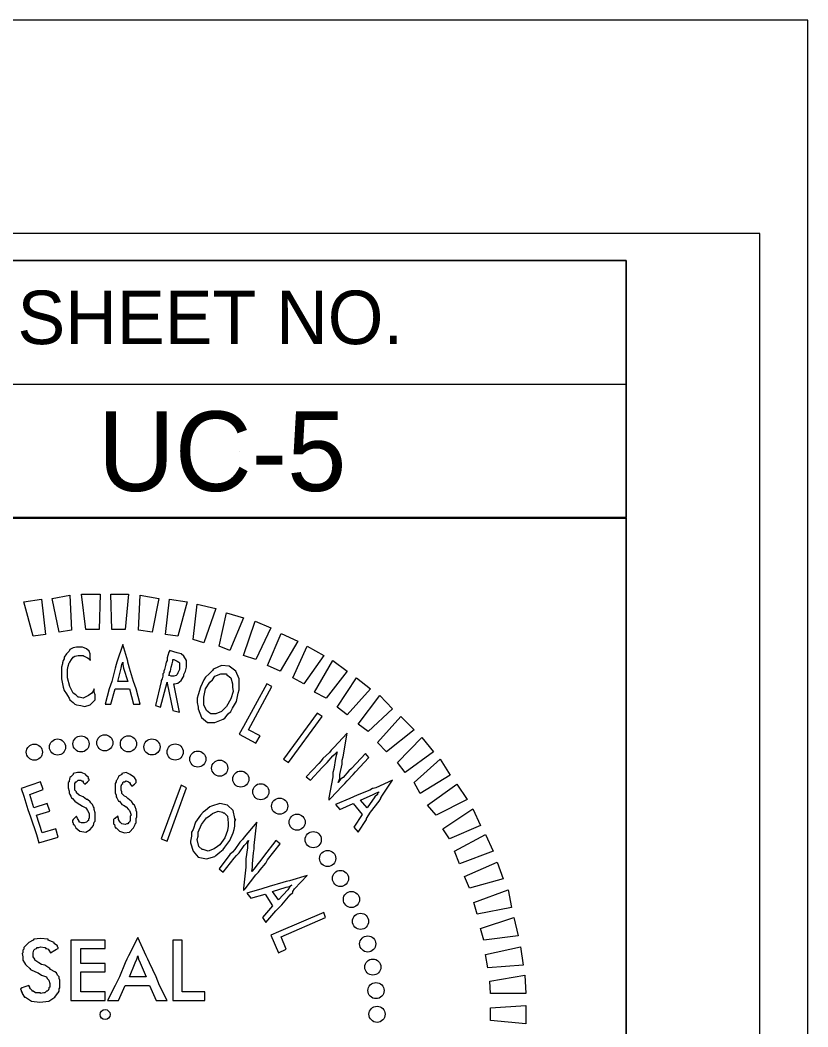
# Model space of a CAD drawing. Extents: x 0 to 2694, y -1 to 1501.
# Drawn here: x 2.7104 to 2.8333, y 1.6762 to 1.8333 of the extents above; entities that cross this region are included whole.
import ezdxf

# ---------------------------------------------------------------- set-up
doc = ezdxf.new("R2010")
doc.units = 0
for name, color, linetype in [('Air Release (M2) CELL', 7, 'Continuous'), ('COGO Default Point Elevation', 7, 'Continuous'), ('Diamond Pattern CELL', 7, 'Continuous')]:
    doc.layers.add(name, color=color, linetype=linetype)

msp = doc.modelspace()

# ---------------------------------------------------------------- linework, layer by layer
at = {"layer": 'Air Release (M2) CELL'}
for p, q in [((2.4719, 1.77648), (2.80496, 1.77648)), ((2.74467, 1.76604), (2.74467, 1.76604)), ((2.72369, 1.67808), (2.72369, 1.67808))]:
    msp.add_line(p, q, dxfattribs=at)
for points in [[(2.4719, 1.79581), (2.80496, 1.79581), (2.80496, 1.75568)], [(2.80496, 1.75568), (2.4719, 1.75568), (2.4719, 1.79581)], [(2.80496, 1.56775), (2.63979, 1.56775), (2.63979, 1.7556), (2.80496, 1.7556)], [(2.80496, 1.7556), (2.80496, 1.56775)]]:
    msp.add_lwpolyline(points, dxfattribs=at)
at = {"layer": 'COGO Default Point Elevation'}
for points in [[(0.02749, 0.00833), (2.83333, 0.00833), (2.83333, 1.83333), (0.02749, 1.83333)], [(0.04916, 0.04166), (2.82583, 0.04166), (2.82583, 1.8), (0.04916, 1.8)], [(2.80499, 1.79583), (0.30499, 1.79583), (0.30499, 0.04583), (2.80499, 0.04583)]]:
    msp.add_lwpolyline(points, close=True, dxfattribs=at)
at = {"layer": 'Diamond Pattern CELL'}
for points in [[(2.7165, 1.73781), (2.71545, 1.74304), (2.7182, 1.74357), (2.71846, 1.73808)], [(2.72068, 1.73821), (2.72003, 1.7437), (2.7229, 1.7437), (2.72277, 1.73821)], [(2.72473, 1.73821), (2.7246, 1.7437), (2.72735, 1.7437), (2.72683, 1.73821)], [(2.72892, 1.73808), (2.72918, 1.74357), (2.73205, 1.74304), (2.73101, 1.73781)], [(2.71245, 1.73716), (2.71101, 1.74252), (2.71376, 1.74291), (2.71441, 1.73742)], [(2.7331, 1.73742), (2.73375, 1.74291), (2.7365, 1.74252), (2.73506, 1.73716)], [(2.73741, 1.73664), (2.73807, 1.74213), (2.74094, 1.74147), (2.73911, 1.73612)], [(2.74147, 1.73559), (2.74264, 1.74082), (2.74526, 1.74004), (2.74317, 1.73494)], [(2.74526, 1.73415), (2.74709, 1.73951), (2.74957, 1.73847), (2.74722, 1.7335)], [(2.74905, 1.73259), (2.75114, 1.73755), (2.75375, 1.73638), (2.75101, 1.73167)], [(2.75297, 1.73063), (2.75519, 1.73559), (2.7578, 1.73415), (2.75467, 1.72971)], [(2.75637, 1.7284), (2.75924, 1.73337), (2.76146, 1.73167), (2.7582, 1.72749)], [(2.7599, 1.72605), (2.7629, 1.73063), (2.76512, 1.72893), (2.76146, 1.72487)], [(2.76316, 1.72344), (2.76656, 1.72788), (2.76852, 1.72579), (2.76473, 1.72226)], [(2.75676, 1.72514), (2.75153, 1.71795), (2.75231, 1.71742), (2.75754, 1.72461)], [(2.76617, 1.72056), (2.76983, 1.72461), (2.77192, 1.72252), (2.76761, 1.71912)], [(2.76931, 1.71742), (2.7731, 1.72135), (2.77493, 1.71912), (2.77048, 1.71586)], [(2.77192, 1.71429), (2.77597, 1.71795), (2.77754, 1.71546), (2.77284, 1.71259)], [(2.73558, 1.71389), (2.73245, 1.70553), (2.73336, 1.70514), (2.73637, 1.7135)], [(2.77401, 1.71076), (2.77859, 1.71403), (2.78016, 1.71167), (2.77532, 1.70919)], [(2.77637, 1.7071), (2.78107, 1.71023), (2.78225, 1.70762), (2.77741, 1.70553)], [(2.7782, 1.70357), (2.78303, 1.70618), (2.78421, 1.70357), (2.77898, 1.70161)], [(2.77976, 1.69965), (2.78486, 1.70187), (2.78578, 1.69926), (2.78055, 1.69782)], [(2.7812, 1.6956), (2.78656, 1.69756), (2.78708, 1.69481), (2.78172, 1.69377)], [(2.78225, 1.69154), (2.78748, 1.69324), (2.78813, 1.69037), (2.78277, 1.68971)], [(2.78303, 1.68749), (2.78852, 1.68867), (2.78891, 1.68579), (2.78342, 1.6854)], [(2.78369, 1.68331), (2.78918, 1.68422), (2.78931, 1.68135), (2.78382, 1.68135)], [(2.78382, 1.67913), (2.78931, 1.67952), (2.78931, 1.67664), (2.78382, 1.67716)]]:
    msp.add_lwpolyline(points, close=True, dxfattribs=at)
for points in [[(2.72134, 1.73442), (2.72121, 1.73481), (2.72081, 1.7352), (2.72042, 1.73533), (2.72016, 1.73546), (2.71925, 1.73546), (2.71872, 1.73533), (2.7182, 1.73507), (2.71807, 1.73481), (2.71768, 1.73442), (2.71728, 1.73389), (2.71728, 1.73376), (2.71728, 1.73363), (2.71715, 1.73337), (2.71702, 1.73298), (2.71702, 1.73285), (2.71689, 1.73232), (2.71689, 1.7318), (2.71689, 1.73049), (2.71715, 1.72919), (2.71728, 1.72866), (2.71768, 1.72814), (2.71781, 1.72788), (2.71807, 1.72749), (2.7182, 1.72723), (2.71872, 1.72683), (2.71898, 1.72657), (2.71925, 1.72644), (2.7199, 1.72631), (2.72055, 1.72618), (2.72134, 1.72644), (2.7216, 1.7267), (2.72186, 1.72697), (2.72212, 1.72723), (2.72212, 1.72775), (2.72212, 1.72801), (2.72199, 1.7284), (2.72199, 1.72866), (2.72199, 1.72893), (2.72186, 1.72866), (2.7216, 1.72827), (2.72108, 1.72788), (2.72029, 1.72749), (2.71964, 1.72762), (2.71951, 1.72762), (2.71911, 1.72801), (2.71872, 1.72827), (2.71846, 1.7288), (2.7182, 1.72932), (2.71781, 1.73063), (2.71781, 1.73193), (2.71794, 1.73246), (2.71807, 1.73298), (2.7182, 1.73311), (2.71846, 1.7335), (2.71872, 1.73389), (2.71898, 1.73402), (2.71951, 1.73415), (2.72029, 1.73415), (2.72042, 1.73402), (2.72094, 1.73376), (2.72134, 1.7335), (2.72134, 1.73337), (2.72134, 1.7335), (2.72134, 1.73389), (2.72134, 1.73415), (2.72134, 1.73429), (2.72134, 1.73442), (2.72134, 1.73442)], [(2.72722, 1.73311), (2.72722, 1.73324), (2.72643, 1.73585), (2.72552, 1.73311), (2.72539, 1.73272), (2.72526, 1.73219), (2.72473, 1.7301), (2.72434, 1.72893), (2.72369, 1.72657), (2.7246, 1.72657), (2.72526, 1.72893), (2.72748, 1.72893), (2.72813, 1.72657), (2.72918, 1.72657), (2.72853, 1.72893), (2.72813, 1.7301), (2.72748, 1.73219), (2.72735, 1.73272), (2.72722, 1.73311), (2.72722, 1.73311)], [(2.73637, 1.73298), (2.73637, 1.73337), (2.73598, 1.73402), (2.73558, 1.73442), (2.73493, 1.73455), (2.73375, 1.73494), (2.73375, 1.73481), (2.73362, 1.73468), (2.73349, 1.73415), (2.73336, 1.73376), (2.73336, 1.73363), (2.73336, 1.7335), (2.73336, 1.73337), (2.73323, 1.73311), (2.7331, 1.73259), (2.73297, 1.73193), (2.73284, 1.73167), (2.73284, 1.73141), (2.73271, 1.73128), (2.73271, 1.73089), (2.73258, 1.73049), (2.73245, 1.73023), (2.73245, 1.7301), (2.73153, 1.72631), (2.73232, 1.72605), (2.73336, 1.72997), (2.73336, 1.72984), (2.73428, 1.72553), (2.73532, 1.72527), (2.73441, 1.72971), (2.73454, 1.72971), (2.73506, 1.72984), (2.73558, 1.73023), (2.73571, 1.73049), (2.73585, 1.73076), (2.73598, 1.73089), (2.73598, 1.73115), (2.73624, 1.73167), (2.73637, 1.73232), (2.73637, 1.73259), (2.73637, 1.73272), (2.73637, 1.73298)], [(2.72643, 1.73311), (2.72643, 1.73272), (2.72656, 1.73219), (2.72722, 1.7301), (2.72565, 1.7301), (2.72617, 1.73219), (2.7263, 1.73272), (2.72643, 1.73311), (2.72643, 1.73311)], [(2.73441, 1.7335), (2.73493, 1.73324), (2.73519, 1.73311), (2.73532, 1.73298), (2.73532, 1.73259), (2.73532, 1.73193), (2.73506, 1.73141), (2.73493, 1.73115), (2.7348, 1.73102), (2.73441, 1.73089), (2.73402, 1.73089), (2.73375, 1.73102), (2.73362, 1.73102), (2.73375, 1.73128), (2.73375, 1.73141), (2.73388, 1.73167), (2.73402, 1.73232), (2.73415, 1.73285), (2.73428, 1.73324), (2.73428, 1.73337), (2.73428, 1.7335), (2.73441, 1.7335), (2.73441, 1.7335)], [(2.74186, 1.73259), (2.74068, 1.73206), (2.74055, 1.73193), (2.74042, 1.7318), (2.7399, 1.73128), (2.73937, 1.73076), (2.73911, 1.73036), (2.73859, 1.72919), (2.7382, 1.72801), (2.73807, 1.72749), (2.73807, 1.72683), (2.7382, 1.72605), (2.7382, 1.72579), (2.73872, 1.72448), (2.73964, 1.7237), (2.74081, 1.7237), (2.74212, 1.72422), (2.74238, 1.72435), (2.7429, 1.72501), (2.7433, 1.7254), (2.74356, 1.72592), (2.74421, 1.72697), (2.74447, 1.72827), (2.7446, 1.7288), (2.7446, 1.72932), (2.7446, 1.7301), (2.7446, 1.73036), (2.7446, 1.73049), (2.74408, 1.73167), (2.74303, 1.73246), (2.74186, 1.73259), (2.74186, 1.73259)], [(2.74264, 1.73128), (2.74264, 1.73115), (2.7433, 1.73063), (2.74356, 1.72971), (2.74356, 1.72919), (2.74369, 1.72853), (2.7433, 1.72736), (2.74264, 1.72618), (2.74225, 1.72579), (2.74186, 1.7254), (2.74094, 1.72501), (2.74029, 1.72501), (2.74016, 1.72501), (2.74003, 1.72514), (2.73951, 1.72553), (2.73911, 1.72644), (2.73911, 1.7271), (2.73911, 1.72762), (2.73937, 1.72893), (2.74003, 1.72997), (2.74042, 1.73036), (2.74081, 1.73089), (2.74173, 1.73128), (2.74251, 1.73128), (2.74264, 1.73128), (2.74264, 1.73128)], [(2.74526, 1.72304), (2.7446, 1.72187), (2.74722, 1.72043), (2.74787, 1.72161), (2.74604, 1.72252), (2.7497, 1.72932), (2.74892, 1.72971), (2.74526, 1.72304), (2.74526, 1.72304)], [(2.76003, 1.71429), (2.76029, 1.71494), (2.76029, 1.71559), (2.76068, 1.71716), (2.76068, 1.71782), (2.76081, 1.71834), (2.76146, 1.722), (2.75937, 1.71978), (2.75898, 1.71938), (2.75872, 1.71899), (2.75767, 1.71808), (2.75741, 1.71769), (2.75702, 1.71729), (2.75506, 1.7152), (2.75571, 1.71468), (2.75754, 1.71664), (2.75794, 1.71703), (2.75833, 1.71742), (2.75924, 1.71847), (2.75963, 1.71886), (2.7599, 1.71912), (2.75977, 1.71873), (2.75963, 1.71808), (2.75937, 1.71638), (2.75924, 1.71586), (2.75924, 1.7152), (2.75859, 1.71193), (2.75859, 1.71154), (2.75885, 1.7118), (2.76068, 1.71376), (2.76107, 1.71416), (2.76146, 1.71455), (2.76238, 1.71559), (2.76277, 1.71599), (2.76486, 1.71821), (2.76434, 1.71886), (2.76212, 1.71651), (2.76173, 1.71612), (2.76081, 1.71507), (2.76042, 1.71481), (2.76003, 1.71429), (2.76003, 1.71429)], [(2.71872, 1.71559), (2.71833, 1.7152), (2.7182, 1.71507), (2.71807, 1.71455), (2.71807, 1.71442), (2.71794, 1.71429), (2.71794, 1.71416), (2.71794, 1.71403), (2.71794, 1.71389), (2.71794, 1.71363), (2.71794, 1.7135), (2.71807, 1.71298), (2.71807, 1.71272), (2.7182, 1.71246), (2.71833, 1.7122), (2.71846, 1.71193), (2.71859, 1.7118), (2.71898, 1.71141), (2.71951, 1.71102), (2.71977, 1.71089), (2.72016, 1.71063), (2.72068, 1.71037), (2.72081, 1.71023), (2.72094, 1.70997), (2.72121, 1.70945), (2.72121, 1.70932), (2.72121, 1.70893), (2.72121, 1.7088), (2.72108, 1.70854), (2.72108, 1.7084), (2.72094, 1.70827), (2.72081, 1.70814), (2.72042, 1.70801), (2.72003, 1.70801), (2.71977, 1.70814), (2.71964, 1.70814), (2.71964, 1.70827), (2.71951, 1.70854), (2.71938, 1.70867), (2.71925, 1.70906), (2.71885, 1.70867), (2.71872, 1.70854), (2.71859, 1.7084), (2.71859, 1.70814), (2.71872, 1.70801), (2.71872, 1.70788), (2.71872, 1.70775), (2.71885, 1.70775), (2.71911, 1.70723), (2.71977, 1.70671), (2.72068, 1.70657), (2.72134, 1.70697), (2.72186, 1.70762), (2.72199, 1.70814), (2.72212, 1.70827), (2.72212, 1.70854), (2.72212, 1.70867), (2.72212, 1.70893), (2.72212, 1.70906), (2.72212, 1.70945), (2.72212, 1.70958), (2.72199, 1.7101), (2.72199, 1.71037), (2.72186, 1.7105), (2.72173, 1.71089), (2.72147, 1.71115), (2.72134, 1.71128), (2.72094, 1.71167), (2.72081, 1.71167), (2.72029, 1.71206), (2.72003, 1.7122), (2.71964, 1.71233), (2.71925, 1.71272), (2.71925, 1.71285), (2.71898, 1.71311), (2.71898, 1.71363), (2.71898, 1.71376), (2.71898, 1.71416), (2.71911, 1.71442), (2.71925, 1.71442), (2.71938, 1.71455), (2.71951, 1.71468), (2.7199, 1.71468), (2.72003, 1.71455), (2.72016, 1.71455), (2.72029, 1.71442), (2.72029, 1.71429), (2.72055, 1.71403), (2.72094, 1.71442), (2.72108, 1.71455), (2.72121, 1.71468), (2.72121, 1.71481), (2.72108, 1.71481), (2.72108, 1.71494), (2.72108, 1.71507), (2.72068, 1.71546), (2.72068, 1.71559), (2.72003, 1.71586), (2.71938, 1.71586), (2.71872, 1.71572), (2.71872, 1.71559), (2.71872, 1.71559)], [(2.7263, 1.71559), (2.72578, 1.71533), (2.72578, 1.7152), (2.72552, 1.71468), (2.72539, 1.71455), (2.72539, 1.71442), (2.72526, 1.71416), (2.72526, 1.71376), (2.72526, 1.71363), (2.72526, 1.71311), (2.72526, 1.71285), (2.72526, 1.71272), (2.72539, 1.71233), (2.72539, 1.71206), (2.72552, 1.71193), (2.72578, 1.71141), (2.72591, 1.71141), (2.7263, 1.71089), (2.72656, 1.71076), (2.72696, 1.7105), (2.72735, 1.7101), (2.72748, 1.70997), (2.72761, 1.70971), (2.72774, 1.70919), (2.72761, 1.70906), (2.72761, 1.70867), (2.72761, 1.70854), (2.72761, 1.7084), (2.72748, 1.70814), (2.72735, 1.70801), (2.72722, 1.70788), (2.72709, 1.70788), (2.72683, 1.70775), (2.7263, 1.70788), (2.72604, 1.70814), (2.72591, 1.70827), (2.72578, 1.70854), (2.72578, 1.70867), (2.72565, 1.70906), (2.72526, 1.70867), (2.72513, 1.70867), (2.725, 1.70854), (2.725, 1.70827), (2.725, 1.70814), (2.725, 1.70788), (2.72513, 1.70775), (2.72526, 1.70723), (2.72539, 1.70723), (2.72591, 1.70671), (2.7267, 1.70644), (2.72748, 1.70657), (2.72813, 1.70723), (2.72839, 1.70775), (2.72839, 1.70788), (2.72853, 1.70801), (2.72853, 1.70814), (2.72853, 1.7084), (2.72853, 1.70854), (2.72853, 1.70867), (2.72866, 1.70893), (2.72866, 1.70919), (2.72866, 1.70971), (2.72853, 1.70997), (2.72853, 1.7101), (2.72839, 1.7105), (2.72826, 1.71076), (2.72813, 1.71089), (2.72787, 1.71128), (2.72774, 1.71141), (2.72722, 1.7118), (2.72696, 1.71206), (2.7267, 1.7122), (2.7263, 1.71259), (2.7263, 1.71285), (2.72617, 1.71311), (2.72617, 1.71363), (2.72617, 1.71376), (2.7263, 1.71403), (2.72643, 1.71416), (2.72643, 1.71429), (2.72656, 1.71442), (2.7267, 1.71442), (2.72696, 1.71455), (2.72735, 1.71442), (2.72748, 1.71429), (2.72761, 1.71416), (2.72761, 1.71403), (2.72787, 1.71376), (2.72826, 1.71403), (2.72839, 1.71416), (2.72853, 1.71429), (2.72853, 1.71442), (2.72853, 1.71455), (2.72853, 1.71468), (2.72826, 1.71507), (2.72813, 1.7152), (2.72761, 1.71559), (2.72696, 1.71586), (2.7263, 1.71572), (2.7263, 1.71559), (2.7263, 1.71559)], [(2.76695, 1.71233), (2.76852, 1.71468), (2.76591, 1.7135), (2.76552, 1.71337), (2.76539, 1.71337), (2.76499, 1.71311), (2.76303, 1.71233), (2.76186, 1.7118), (2.75963, 1.71089), (2.76029, 1.7101), (2.76238, 1.71102), (2.76382, 1.70932), (2.76251, 1.70736), (2.76316, 1.70657), (2.76447, 1.70854), (2.76447, 1.70867), (2.76512, 1.70971), (2.76643, 1.71141), (2.76669, 1.7118), (2.76669, 1.71193), (2.76695, 1.71233), (2.76695, 1.71233)], [(2.71297, 1.70618), (2.71336, 1.70488), (2.71637, 1.70579), (2.71598, 1.7071), (2.71389, 1.70644), (2.71297, 1.70919), (2.71506, 1.70984), (2.71467, 1.71102), (2.71258, 1.71037), (2.71193, 1.71246), (2.71402, 1.71324), (2.71362, 1.71442), (2.71062, 1.71337), (2.71101, 1.7122), (2.71166, 1.7101), (2.71206, 1.70893), (2.71297, 1.70618), (2.71297, 1.70618)], [(2.76643, 1.71285), (2.76617, 1.71259), (2.76617, 1.71246), (2.76578, 1.71206), (2.7646, 1.71037), (2.76356, 1.71154), (2.76552, 1.71246), (2.76604, 1.71272), (2.76643, 1.71285), (2.76643, 1.71285)], [(2.7416, 1.71102), (2.74029, 1.71063), (2.74003, 1.7105), (2.73937, 1.70997), (2.73898, 1.70971), (2.73859, 1.70919), (2.73781, 1.70814), (2.73741, 1.70697), (2.73715, 1.70657), (2.73715, 1.70592), (2.73702, 1.70514), (2.73702, 1.70488), (2.73741, 1.70357), (2.7382, 1.70265), (2.73951, 1.70239), (2.74081, 1.70278), (2.74094, 1.70291), (2.7416, 1.70344), (2.74212, 1.70383), (2.74238, 1.70422), (2.74317, 1.70527), (2.74369, 1.70644), (2.74382, 1.70697), (2.74395, 1.70749), (2.74395, 1.70827), (2.74408, 1.70854), (2.74395, 1.70854), (2.74395, 1.70867), (2.74369, 1.70997), (2.74277, 1.71076), (2.7416, 1.71102), (2.7416, 1.71102)], [(2.74212, 1.70958), (2.74225, 1.70958), (2.74277, 1.70906), (2.7429, 1.70801), (2.7429, 1.70749), (2.74277, 1.70684), (2.74238, 1.70566), (2.7416, 1.70461), (2.7412, 1.70435), (2.74068, 1.70396), (2.73977, 1.70357), (2.73898, 1.70383), (2.73885, 1.70383), (2.73833, 1.70435), (2.73807, 1.7054), (2.7382, 1.70592), (2.7382, 1.70657), (2.73872, 1.70775), (2.73951, 1.7088), (2.7399, 1.70906), (2.74042, 1.70945), (2.74134, 1.70984), (2.74199, 1.70971), (2.74212, 1.70958), (2.74212, 1.70958)], [(2.74656, 1.70043), (2.74669, 1.70109), (2.74669, 1.70161), (2.74683, 1.70331), (2.74696, 1.70396), (2.74696, 1.70448), (2.74735, 1.70814), (2.74539, 1.70579), (2.74513, 1.7054), (2.74473, 1.70501), (2.74395, 1.70383), (2.74356, 1.70344), (2.74317, 1.70305), (2.74147, 1.70082), (2.74212, 1.7003), (2.74382, 1.70252), (2.74421, 1.70291), (2.7446, 1.70331), (2.74539, 1.70448), (2.74578, 1.70488), (2.74604, 1.70527), (2.74591, 1.70474), (2.74591, 1.70409), (2.74565, 1.70239), (2.74565, 1.70187), (2.74565, 1.70109), (2.74526, 1.69782), (2.74526, 1.69743), (2.74552, 1.69769), (2.74722, 1.69991), (2.74761, 1.7003), (2.74787, 1.70069), (2.74879, 1.70174), (2.74905, 1.70226), (2.75101, 1.70474), (2.75035, 1.70527), (2.74839, 1.70278), (2.74813, 1.70239), (2.74722, 1.70122), (2.74696, 1.70082), (2.74656, 1.70043), (2.74656, 1.70043)], [(2.75323, 1.69769), (2.75519, 1.69978), (2.75245, 1.69899), (2.75192, 1.69886), (2.7514, 1.69873), (2.74931, 1.69808), (2.74813, 1.69769), (2.74578, 1.69703), (2.74643, 1.69625), (2.74865, 1.6969), (2.74983, 1.69507), (2.74826, 1.69324), (2.74879, 1.69246), (2.75035, 1.69429), (2.75127, 1.6952), (2.75258, 1.69677), (2.75297, 1.69716), (2.75297, 1.69729), (2.75323, 1.69769), (2.75323, 1.69769)], [(2.75284, 1.69834), (2.75245, 1.69795), (2.75218, 1.69756), (2.75075, 1.69599), (2.74983, 1.69729), (2.75192, 1.69795), (2.75245, 1.69808), (2.75284, 1.69834), (2.75284, 1.69834)], [(2.75075, 1.69102), (2.74957, 1.6905), (2.75075, 1.68775), (2.75192, 1.68828), (2.75114, 1.69024), (2.75807, 1.69324), (2.7578, 1.69403), (2.75075, 1.69102), (2.75075, 1.69102)], [(2.71245, 1.68971), (2.71179, 1.68932), (2.71166, 1.68919), (2.71127, 1.6888), (2.71114, 1.68867), (2.71101, 1.68854), (2.71101, 1.68841), (2.71101, 1.68828), (2.71088, 1.68814), (2.71088, 1.68775), (2.71075, 1.68762), (2.71088, 1.6871), (2.71088, 1.68671), (2.71088, 1.68658), (2.71114, 1.68618), (2.71127, 1.68592), (2.7114, 1.68579), (2.71193, 1.68527), (2.71206, 1.68514), (2.71284, 1.68475), (2.71323, 1.68462), (2.71376, 1.68422), (2.71454, 1.68396), (2.71467, 1.6837), (2.71493, 1.68344), (2.71506, 1.68292), (2.71506, 1.68279), (2.71506, 1.68239), (2.71493, 1.68226), (2.71493, 1.68213), (2.7148, 1.68187), (2.71467, 1.68174), (2.71454, 1.68174), (2.71428, 1.68148), (2.71415, 1.68148), (2.71362, 1.68135), (2.71362, 1.68148), (2.71284, 1.68148), (2.71245, 1.68174), (2.71232, 1.68174), (2.71232, 1.68187), (2.71206, 1.68213), (2.71193, 1.68226), (2.71193, 1.68239), (2.71179, 1.68265), (2.71101, 1.68239), (2.71075, 1.68226), (2.71049, 1.68213), (2.71062, 1.68187), (2.71062, 1.68174), (2.71075, 1.68148), (2.71075, 1.68135), (2.71114, 1.68082), (2.71127, 1.68082), (2.71219, 1.68017), (2.71349, 1.68004), (2.71493, 1.68017), (2.71585, 1.68082), (2.71624, 1.68135), (2.71624, 1.68148), (2.71637, 1.68148), (2.7165, 1.68174), (2.7165, 1.68187), (2.7165, 1.68213), (2.71663, 1.68226), (2.71663, 1.68239), (2.71663, 1.68279), (2.71663, 1.68292), (2.71663, 1.68344), (2.7165, 1.6837), (2.7165, 1.68396), (2.71624, 1.68422), (2.71611, 1.68462), (2.71585, 1.68475), (2.71519, 1.68514), (2.71506, 1.68527), (2.71428, 1.68579), (2.71376, 1.68592), (2.71336, 1.68618), (2.71271, 1.68658), (2.71271, 1.68671), (2.71245, 1.6871), (2.71245, 1.68762), (2.71245, 1.68775), (2.71258, 1.68814), (2.71271, 1.68828), (2.71297, 1.68841), (2.7131, 1.68854), (2.71336, 1.68854), (2.71362, 1.68867), (2.71428, 1.68854), (2.71441, 1.68854), (2.71441, 1.68841), (2.71454, 1.68841), (2.7148, 1.68828), (2.71493, 1.68814), (2.71519, 1.68775), (2.71585, 1.68814), (2.71611, 1.68828), (2.71637, 1.68841), (2.71637, 1.68854), (2.71624, 1.68867), (2.71624, 1.6888), (2.71572, 1.68919), (2.71572, 1.68932), (2.7148, 1.68971), (2.7148, 1.68984), (2.71362, 1.68997), (2.71258, 1.68984), (2.71245, 1.68971), (2.71245, 1.68971)], [(2.71833, 1.68161), (2.71833, 1.6803), (2.72369, 1.6803), (2.72369, 1.68161), (2.7199, 1.68161), (2.7199, 1.68475), (2.72369, 1.68475), (2.72369, 1.68605), (2.7199, 1.68605), (2.7199, 1.68841), (2.72369, 1.68841), (2.72369, 1.68971), (2.71833, 1.68971), (2.71833, 1.68841), (2.71833, 1.68605), (2.71833, 1.68475), (2.71833, 1.68161), (2.71833, 1.68161)], [(2.73009, 1.68723), (2.72879, 1.69011), (2.72735, 1.68723), (2.72709, 1.68671), (2.72683, 1.68618), (2.72591, 1.68396), (2.72526, 1.68265), (2.72408, 1.6803), (2.72578, 1.6803), (2.72683, 1.68265), (2.73062, 1.68265), (2.73166, 1.6803), (2.73336, 1.6803), (2.73219, 1.68265), (2.73166, 1.68396), (2.73062, 1.68618), (2.73036, 1.68671), (2.73009, 1.68723), (2.73009, 1.68723)], [(2.73428, 1.68161), (2.73428, 1.6803), (2.73924, 1.6803), (2.73924, 1.68161), (2.73571, 1.68161), (2.73571, 1.68971), (2.73428, 1.68971), (2.73428, 1.68161), (2.73428, 1.68161)], [(2.72879, 1.68723), (2.72892, 1.68671), (2.72918, 1.68618), (2.73009, 1.68396), (2.72748, 1.68396), (2.72839, 1.68618), (2.72866, 1.68671), (2.72879, 1.68723), (2.72879, 1.68723)]]:
    msp.add_lwpolyline(points, dxfattribs=at)
for centre, radius in [((2.71627, 1.71985), 0.00126), ((2.71994, 1.72034), 0.00126), ((2.72364, 1.72051), 0.00126), ((2.72733, 1.72035), 0.00126), ((2.731, 1.71987), 0.00126), ((2.71266, 1.71905), 0.00126), ((2.73462, 1.71908), 0.00126), ((2.73815, 1.71797), 0.00126), ((2.74157, 1.71656), 0.00126), ((2.74486, 1.71485), 0.00126), ((2.74798, 1.71287), 0.00126), ((2.75092, 1.71062), 0.00126), ((2.75365, 1.70812), 0.00126), ((2.75616, 1.70539), 0.00126), ((2.75841, 1.70246), 0.00126), ((2.76041, 1.69934), 0.00126), ((2.76212, 1.69606), 0.00126), ((2.76354, 1.69264), 0.00126), ((2.76466, 1.68911), 0.00126), ((2.76546, 1.6855), 0.00126), ((2.76595, 1.68183), 0.00126), ((2.72369, 1.67808), 0.000784), ((2.76612, 1.67813), 0.00126)]:
    msp.add_circle(centre, radius, dxfattribs=at)

# ---------------------------------------------------------------- texts
at = {"layer": 'Air Release (M2) CELL'}
msp.add_text('SHEET NO.', height=0.008352, dxfattribs=at).set_placement((2.71002, 1.78275))
at = {"layer": 'COGO Default Point Elevation'}
msp.add_text('UC-5', height=0.01243, dxfattribs=at).set_placement((2.72255, 1.75982))

doc.saveas('drawing.dxf')
